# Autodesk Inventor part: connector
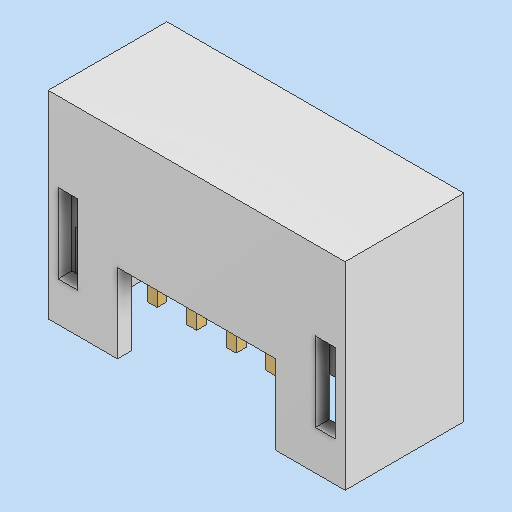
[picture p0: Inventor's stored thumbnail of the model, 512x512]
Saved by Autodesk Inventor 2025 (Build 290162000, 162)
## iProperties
Created: 2025-05
Part Number: connector
Material: Generico
Description: connector
Document SubType Name: Modeling
Designer: R5800u
Density: 1 g/cm^3
Appearance: Default
Author: R5800u
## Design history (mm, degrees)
feature "Base1"
node "Solido1"
